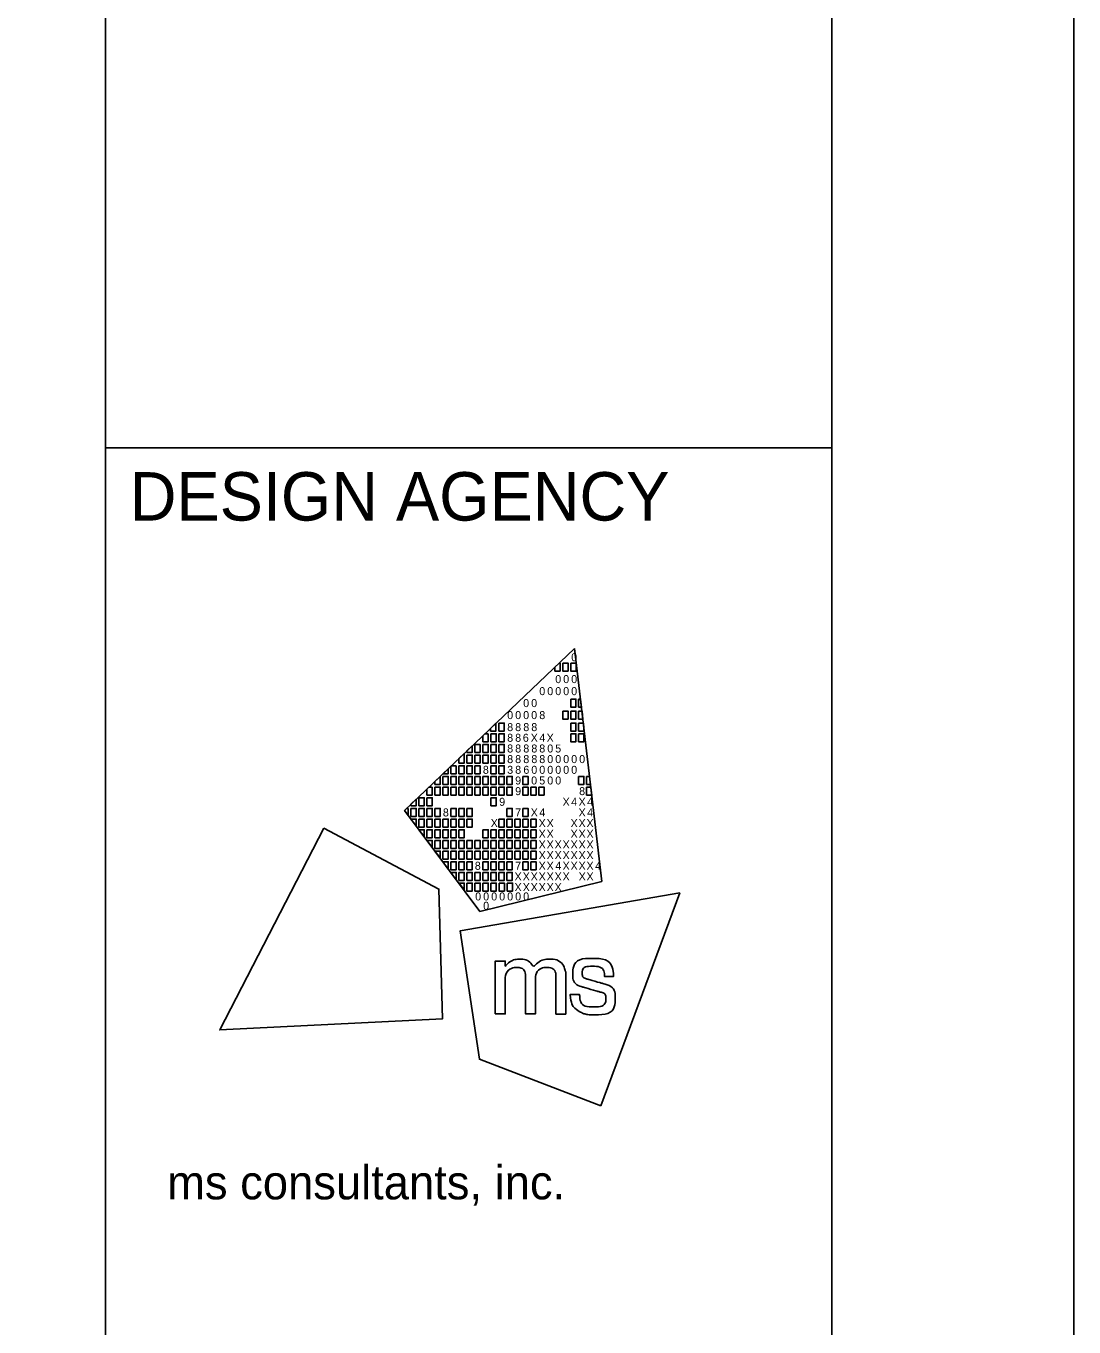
# Model space of a CAD drawing. Extents: x -0.6 to 34, y 0 to 22.
# Drawn here: x 31.836 to 34, y 2.685 to 5.371 of the extents above; entities that cross this region are included whole.
import ezdxf

# ---------------------------------------------------------------- set-up
doc = ezdxf.new("R2010")
doc.units = 0
for name, color, linetype in [('Default', 7, 'Continuous'), ('SH_Border', 7, 'Continuous'), ('SH_Cut_Line', 7, 'Continuous'), ('SH_Data', 7, 'Continuous')]:
    doc.layers.add(name, color=color, linetype=linetype)

msp = doc.modelspace()

# ---------------------------------------------------------------- linework, layer by layer
at = {"layer": 'Default'}
for p, q in [((32.6175, 3.7519), (32.9688, 4.0861)), ((32.9688, 4.0861), (32.9688, 4.0861)), ((32.9688, 4.0861), (33.0253, 3.6052)), ((32.773, 3.543), (32.6175, 3.7519)), ((33.0253, 3.6052), (32.773, 3.543))]:
    msp.add_line(p, q, dxfattribs=at)
for points in [[(32.9279, 4.0472), (32.9369, 4.0558), (32.9389, 4.0558), (32.9389, 4.0393), (32.9279, 4.0393)], [(32.9444, 4.0558), (32.9554, 4.0558), (32.9554, 4.0393), (32.9444, 4.0393)], [(32.9609, 4.0558), (32.9719, 4.0558), (32.9719, 4.0393), (32.9609, 4.0393)], [(32.9606, 3.9815), (32.9716, 3.9815), (32.9716, 3.965), (32.9606, 3.965)], [(32.9771, 3.9815), (32.9811, 3.9815), (32.983, 3.965), (32.9771, 3.965)], [(32.9441, 3.9567), (32.9551, 3.9567), (32.9551, 3.9402), (32.9441, 3.9402)], [(32.9606, 3.9567), (32.9716, 3.9567), (32.9716, 3.9402), (32.9606, 3.9402)], [(32.9771, 3.9567), (32.984, 3.9567), (32.9859, 3.9402), (32.9771, 3.9402)], [(32.7953, 3.9211), (32.8064, 3.9316), (32.8064, 3.9154), (32.7953, 3.9154)], [(32.8123, 3.9319), (32.8233, 3.9319), (32.8233, 3.9154), (32.8123, 3.9154)], [(32.9606, 3.9319), (32.9716, 3.9319), (32.9716, 3.9154), (32.9606, 3.9154)], [(32.9771, 3.9319), (32.9869, 3.9319), (32.9881, 3.9218), (32.9881, 3.9154), (32.9771, 3.9154)], [(32.7958, 3.9099), (32.8068, 3.9099), (32.8068, 3.8934), (32.7958, 3.8934)], [(32.8123, 3.9099), (32.8233, 3.9099), (32.8233, 3.8934), (32.8123, 3.8934)], [(32.9606, 3.9099), (32.9716, 3.9099), (32.9716, 3.8934), (32.9606, 3.8934)], [(32.9771, 3.9099), (32.9881, 3.9099), (32.9881, 3.8934), (32.9771, 3.8934)], [(32.7627, 3.8879), (32.7737, 3.8879), (32.7737, 3.8714), (32.7627, 3.8714)], [(32.7793, 3.8879), (32.7903, 3.8879), (32.7903, 3.8714), (32.7793, 3.8714)], [(32.7958, 3.8879), (32.8068, 3.8879), (32.8068, 3.8714), (32.7958, 3.8714)], [(32.8123, 3.8879), (32.8233, 3.8879), (32.8233, 3.8714), (32.8123, 3.8714)], [(32.7297, 3.8439), (32.7407, 3.8439), (32.7407, 3.8273), (32.7297, 3.8273)], [(32.7462, 3.8659), (32.7572, 3.8659), (32.7572, 3.8494), (32.7462, 3.8494)], [(32.7462, 3.8439), (32.7572, 3.8439), (32.7572, 3.8273), (32.7462, 3.8273)], [(32.7627, 3.8659), (32.7737, 3.8659), (32.7737, 3.8494), (32.7627, 3.8494)], [(32.7627, 3.8439), (32.7737, 3.8439), (32.7737, 3.8273), (32.7627, 3.8273)], [(32.7793, 3.8659), (32.7903, 3.8659), (32.7903, 3.8494), (32.7793, 3.8494)], [(32.7958, 3.8659), (32.8068, 3.8659), (32.8068, 3.8494), (32.7958, 3.8494)], [(32.7958, 3.8439), (32.8068, 3.8439), (32.8068, 3.8273), (32.7958, 3.8273)], [(32.8123, 3.8659), (32.8233, 3.8659), (32.8233, 3.8494), (32.8123, 3.8494)], [(32.8123, 3.8439), (32.8233, 3.8439), (32.8233, 3.8273), (32.8123, 3.8273)], [(32.6967, 3.8218), (32.7077, 3.8218), (32.7077, 3.8053), (32.6967, 3.8053)], [(32.7132, 3.8218), (32.7242, 3.8218), (32.7242, 3.8053), (32.7132, 3.8053)], [(32.7297, 3.8218), (32.7407, 3.8218), (32.7407, 3.8053), (32.7297, 3.8053)], [(32.7462, 3.8218), (32.7572, 3.8218), (32.7572, 3.8053), (32.7462, 3.8053)], [(32.7627, 3.8218), (32.7737, 3.8218), (32.7737, 3.8053), (32.7627, 3.8053)], [(32.7793, 3.8218), (32.7903, 3.8218), (32.7903, 3.8053), (32.7793, 3.8053)], [(32.7958, 3.8218), (32.8068, 3.8218), (32.8068, 3.8053), (32.7958, 3.8053)], [(32.8123, 3.8218), (32.8233, 3.8218), (32.8233, 3.8053), (32.8123, 3.8053)], [(32.8288, 3.8218), (32.8398, 3.8218), (32.8398, 3.8053), (32.8288, 3.8053)], [(32.8618, 3.8218), (32.8728, 3.8218), (32.8728, 3.8053), (32.8618, 3.8053)], [(32.9771, 3.8218), (32.9881, 3.8218), (32.9881, 3.8053), (32.9771, 3.8053)], [(32.9935, 3.8218), (32.9998, 3.8218), (33.0018, 3.8053), (32.9935, 3.8053)], [(32.6802, 3.7998), (32.6912, 3.7998), (32.6912, 3.7833), (32.6802, 3.7833)], [(32.6967, 3.7998), (32.7077, 3.7998), (32.7077, 3.7833), (32.6967, 3.7833)], [(32.7132, 3.7998), (32.7242, 3.7998), (32.7242, 3.7833), (32.7132, 3.7833)], [(32.7297, 3.7998), (32.7407, 3.7998), (32.7407, 3.7833), (32.7297, 3.7833)], [(32.7462, 3.7998), (32.7572, 3.7998), (32.7572, 3.7833), (32.7462, 3.7833)], [(32.7627, 3.7998), (32.7737, 3.7998), (32.7737, 3.7833), (32.7627, 3.7833)], [(32.7793, 3.7998), (32.7903, 3.7998), (32.7903, 3.7833), (32.7793, 3.7833)], [(32.7958, 3.7998), (32.8068, 3.7998), (32.8068, 3.7833), (32.7958, 3.7833)], [(32.8123, 3.7998), (32.8233, 3.7998), (32.8233, 3.7833), (32.8123, 3.7833)], [(32.8288, 3.7998), (32.8398, 3.7998), (32.8398, 3.7833), (32.8288, 3.7833)], [(32.8618, 3.7998), (32.8728, 3.7998), (32.8728, 3.7833), (32.8618, 3.7833)], [(32.8783, 3.7998), (32.8893, 3.7998), (32.8893, 3.7833), (32.8783, 3.7833)], [(32.8947, 3.7998), (32.9057, 3.7998), (32.9057, 3.7833), (32.8947, 3.7833)], [(32.9935, 3.7998), (33.0024, 3.7998), (33.0044, 3.7833), (32.9935, 3.7833)], [(32.6471, 3.7778), (32.6581, 3.7778), (32.6581, 3.7613), (32.6471, 3.7613)], [(32.6637, 3.7778), (32.6747, 3.7778), (32.6747, 3.7613), (32.6637, 3.7613)], [(32.7958, 3.7778), (32.8068, 3.7778), (32.8068, 3.7613), (32.7958, 3.7613)], [(32.6306, 3.7558), (32.6416, 3.7558), (32.6416, 3.7393), (32.6306, 3.7393)], [(32.6306, 3.7338), (32.6416, 3.7338), (32.6416, 3.72)], [(32.6471, 3.7558), (32.6581, 3.7558), (32.6581, 3.7393), (32.6471, 3.7393)], [(32.6471, 3.7338), (32.6581, 3.7338), (32.6581, 3.7173), (32.6471, 3.7173)], [(32.6637, 3.7558), (32.6747, 3.7558), (32.6747, 3.7393), (32.6637, 3.7393)], [(32.6637, 3.7338), (32.6747, 3.7338), (32.6747, 3.7173), (32.6637, 3.7173)], [(32.6802, 3.7558), (32.6912, 3.7558), (32.6912, 3.7393), (32.6802, 3.7393)], [(32.6802, 3.7338), (32.6912, 3.7338), (32.6912, 3.7173), (32.6802, 3.7173)], [(32.6967, 3.7338), (32.7077, 3.7338), (32.7077, 3.7173), (32.6967, 3.7173)], [(32.7132, 3.7558), (32.7242, 3.7558), (32.7242, 3.7393), (32.7132, 3.7393)], [(32.7132, 3.7338), (32.7242, 3.7338), (32.7242, 3.7173), (32.7132, 3.7173)], [(32.7297, 3.7558), (32.7407, 3.7558), (32.7407, 3.7393), (32.7297, 3.7393)], [(32.7297, 3.7338), (32.7407, 3.7338), (32.7407, 3.7173), (32.7297, 3.7173)], [(32.7462, 3.7558), (32.7572, 3.7558), (32.7572, 3.7393), (32.7462, 3.7393)], [(32.7462, 3.7338), (32.7572, 3.7338), (32.7572, 3.7173), (32.7462, 3.7173)], [(32.8123, 3.7338), (32.8233, 3.7338), (32.8233, 3.7173), (32.8123, 3.7173)], [(32.8288, 3.7558), (32.8398, 3.7558), (32.8398, 3.7393), (32.8288, 3.7393)], [(32.8288, 3.7338), (32.8398, 3.7338), (32.8398, 3.7173), (32.8288, 3.7173)], [(32.8453, 3.7338), (32.8563, 3.7338), (32.8563, 3.7173), (32.8453, 3.7173)], [(32.8618, 3.7558), (32.8728, 3.7558), (32.8728, 3.7393), (32.8618, 3.7393)], [(32.8618, 3.7338), (32.8728, 3.7338), (32.8728, 3.7173), (32.8618, 3.7173)], [(32.8783, 3.7338), (32.8893, 3.7338), (32.8893, 3.7173), (32.8783, 3.7173)], [(32.6471, 3.7117), (32.6581, 3.7117), (32.6581, 3.698)], [(32.6637, 3.7117), (32.6747, 3.7117), (32.6747, 3.6952), (32.6637, 3.6952)], [(32.6802, 3.7117), (32.6912, 3.7117), (32.6912, 3.6952), (32.6802, 3.6952)], [(32.6967, 3.7117), (32.7077, 3.7117), (32.7077, 3.6952), (32.6967, 3.6952)], [(32.7132, 3.7117), (32.7242, 3.7117), (32.7242, 3.6952), (32.7132, 3.6952)], [(32.7297, 3.7117), (32.7407, 3.7117), (32.7407, 3.6952), (32.7297, 3.6952)], [(32.7793, 3.7117), (32.7903, 3.7117), (32.7903, 3.6952), (32.7793, 3.6952)], [(32.7958, 3.7117), (32.8068, 3.7117), (32.8068, 3.6952), (32.7958, 3.6952)], [(32.8123, 3.7117), (32.8233, 3.7117), (32.8233, 3.6952), (32.8123, 3.6952)], [(32.8288, 3.7117), (32.8398, 3.7117), (32.8398, 3.6952), (32.8288, 3.6952)], [(32.8453, 3.7117), (32.8563, 3.7117), (32.8563, 3.6952), (32.8453, 3.6952)], [(32.8618, 3.7117), (32.8728, 3.7117), (32.8728, 3.6952), (32.8618, 3.6952)], [(32.8783, 3.7117), (32.8893, 3.7117), (32.8893, 3.6952), (32.8783, 3.6952)], [(32.6637, 3.6897), (32.6747, 3.6897), (32.6747, 3.676)], [(32.6747, 3.6897), (32.6747, 3.6897), (32.6747, 3.6897)], [(32.6802, 3.6897), (32.6912, 3.6897), (32.6912, 3.6732), (32.6802, 3.6732)], [(32.6967, 3.6897), (32.7077, 3.6897), (32.7077, 3.6732), (32.6967, 3.6732)], [(32.7132, 3.6897), (32.7242, 3.6897), (32.7242, 3.6732), (32.7132, 3.6732)], [(32.7297, 3.6897), (32.7407, 3.6897), (32.7407, 3.6732), (32.7297, 3.6732)], [(32.7462, 3.6897), (32.7572, 3.6897), (32.7572, 3.6732), (32.7462, 3.6732)], [(32.7627, 3.6897), (32.7737, 3.6897), (32.7737, 3.6732), (32.7627, 3.6732)], [(32.7793, 3.6897), (32.7903, 3.6897), (32.7903, 3.6732), (32.7793, 3.6732)], [(32.7958, 3.6897), (32.8068, 3.6897), (32.8068, 3.6732), (32.7958, 3.6732)], [(32.8123, 3.6897), (32.8233, 3.6897), (32.8233, 3.6732), (32.8123, 3.6732)], [(32.8288, 3.6897), (32.8398, 3.6897), (32.8398, 3.6732), (32.8288, 3.6732)], [(32.8453, 3.6897), (32.8563, 3.6897), (32.8563, 3.6732), (32.8453, 3.6732)], [(32.8618, 3.6897), (32.8728, 3.6897), (32.8728, 3.6732), (32.8618, 3.6732)], [(32.8783, 3.6897), (32.8893, 3.6897), (32.8893, 3.6732), (32.8783, 3.6732)], [(32.6802, 3.6677), (32.6912, 3.6677), (32.6912, 3.654)], [(32.6967, 3.6677), (32.7077, 3.6677), (32.7077, 3.6512), (32.6967, 3.6512)], [(32.7132, 3.6677), (32.7242, 3.6677), (32.7242, 3.6512), (32.7132, 3.6512)], [(32.7297, 3.6677), (32.7407, 3.6677), (32.7407, 3.6512), (32.7297, 3.6512)], [(32.7462, 3.6677), (32.7572, 3.6677), (32.7572, 3.6512), (32.7462, 3.6512)], [(32.7627, 3.6677), (32.7737, 3.6677), (32.7737, 3.6512), (32.7627, 3.6512)], [(32.7793, 3.6677), (32.7903, 3.6677), (32.7903, 3.6512), (32.7793, 3.6512)], [(32.7958, 3.6677), (32.8068, 3.6677), (32.8068, 3.6512), (32.7958, 3.6512)], [(32.8123, 3.6677), (32.8233, 3.6677), (32.8233, 3.6512), (32.8123, 3.6512)], [(32.8288, 3.6677), (32.8398, 3.6677), (32.8398, 3.6512), (32.8288, 3.6512)], [(32.8453, 3.6677), (32.8563, 3.6677), (32.8563, 3.6512), (32.8453, 3.6512)], [(32.8618, 3.6677), (32.8728, 3.6677), (32.8728, 3.6512), (32.8618, 3.6512)], [(32.8783, 3.6677), (32.8893, 3.6677), (32.8893, 3.6512), (32.8783, 3.6512)], [(32.7077, 3.6305), (32.6965, 3.6457), (32.7077, 3.6457)], [(32.7132, 3.6457), (32.7242, 3.6457), (32.7242, 3.6292), (32.7132, 3.6292)], [(32.7297, 3.6457), (32.7407, 3.6457), (32.7407, 3.6292), (32.7297, 3.6292)], [(32.7462, 3.6457), (32.7572, 3.6457), (32.7572, 3.6292), (32.7462, 3.6292)], [(32.7793, 3.6457), (32.7903, 3.6457), (32.7903, 3.6292), (32.7793, 3.6292)], [(32.7958, 3.6457), (32.8068, 3.6457), (32.8068, 3.6292), (32.7958, 3.6292)], [(32.8123, 3.6457), (32.8233, 3.6457), (32.8233, 3.6292), (32.8123, 3.6292)], [(32.8288, 3.6457), (32.8398, 3.6457), (32.8398, 3.6292), (32.8288, 3.6292)], [(32.8618, 3.6457), (32.8728, 3.6457), (32.8728, 3.6292), (32.8618, 3.6292)], [(32.8783, 3.6457), (32.8893, 3.6457), (32.8893, 3.6292), (32.8783, 3.6292)], [(32.724, 3.6082), (32.7132, 3.6237), (32.7242, 3.6237)], [(32.7297, 3.6237), (32.7407, 3.6237), (32.7407, 3.6072), (32.7297, 3.6072)], [(32.7302, 3.6017), (32.7407, 3.6017), (32.7408, 3.5875)], [(32.7462, 3.6237), (32.7572, 3.6237), (32.7572, 3.6072), (32.7462, 3.6072)], [(32.7463, 3.6017), (32.7573, 3.6017), (32.7573, 3.5852), (32.7463, 3.5852)], [(32.7627, 3.6237), (32.7737, 3.6237), (32.7737, 3.6072), (32.7627, 3.6072)], [(32.763, 3.6017), (32.774, 3.6017), (32.774, 3.5852), (32.763, 3.5852)], [(32.7793, 3.6237), (32.7903, 3.6237), (32.7903, 3.6072), (32.7793, 3.6072)], [(32.7794, 3.6017), (32.7904, 3.6017), (32.7904, 3.5852), (32.7794, 3.5852)], [(32.7958, 3.6237), (32.8068, 3.6237), (32.8068, 3.6072), (32.7958, 3.6072)], [(32.796, 3.6017), (32.807, 3.6017), (32.807, 3.5852), (32.796, 3.5852)], [(32.8123, 3.6237), (32.8233, 3.6237), (32.8233, 3.6072), (32.8123, 3.6072)], [(32.8129, 3.6017), (32.8239, 3.6017), (32.8239, 3.5851), (32.8129, 3.5851)], [(32.8288, 3.6237), (32.8398, 3.6237), (32.8398, 3.6072), (32.8288, 3.6072)], [(32.8296, 3.6017), (32.8406, 3.6017), (32.8406, 3.5851), (32.8296, 3.5851)]]:
    msp.add_lwpolyline(points, close=True, dxfattribs=at)
for points in [[(32.7903, 3.9099), (32.7836, 3.9099), (32.7793, 3.9058), (32.7793, 3.8934), (32.7903, 3.8934), (32.7903, 3.9099)], [(32.7407, 3.8691), (32.7297, 3.8587), (32.7297, 3.8494), (32.7407, 3.8494), (32.7407, 3.8691)], [(32.7572, 3.8849), (32.7462, 3.8744), (32.7462, 3.8714), (32.7572, 3.8714), (32.7572, 3.8849)], [(32.7242, 3.8439), (32.7141, 3.8439), (32.7132, 3.843), (32.7132, 3.8273), (32.7242, 3.8273), (32.7242, 3.8439)], [(32.6912, 3.822), (32.6802, 3.8115), (32.6802, 3.8053), (32.6912, 3.8053), (32.6912, 3.822)], [(32.7077, 3.8377), (32.6968, 3.8273), (32.7077, 3.8273), (32.7077, 3.8377)], [(32.6747, 3.7998), (32.6679, 3.7998), (32.6637, 3.7958), (32.6637, 3.7833), (32.6747, 3.7833), (32.6747, 3.7998)], [(32.6416, 3.7749), (32.6306, 3.7644), (32.6306, 3.7613), (32.6416, 3.7613), (32.6416, 3.7749)], [(32.6251, 3.7558), (32.6216, 3.7558), (32.6175, 3.7519), (32.6251, 3.7417), (32.6251, 3.7558)], [(32.4512, 3.7149), (32.2359, 3.2988), (32.6956, 3.3215), (32.6884, 3.5892), (32.4512, 3.7149)], [(33.0229, 3.1422), (33.1859, 3.5814), (32.7324, 3.5029), (32.7722, 3.2381), (33.0229, 3.1422)]]:
    msp.add_lwpolyline(points, dxfattribs=at)
for points in [[(32.8048, 3.3315), (32.8048, 3.3315), (32.8048, 3.4409), (32.8048, 3.4409), (32.8048, 3.4409), (32.8255, 3.4409), (32.8255, 3.4409), (32.8255, 3.4409), (32.8255, 3.4297), (32.8255, 3.4297), (32.8346, 3.4399), (32.8457, 3.4445), (32.8555, 3.4445), (32.8688, 3.4445), (32.8791, 3.4372), (32.8837, 3.4266), (32.8915, 3.4381), (32.905, 3.4446), (32.9166, 3.4446), (32.9325, 3.4446), (32.9451, 3.435), (32.9494, 3.4213), (32.9494, 3.4212), (32.9494, 3.4212), (32.9494, 3.4212), (32.9501, 3.419), (32.9506, 3.4172), (32.9506, 3.4071), (32.9506, 3.4071), (32.9506, 3.3314), (32.9506, 3.3314), (32.9506, 3.3314), (32.9303, 3.3314), (32.9303, 3.3314), (32.9303, 3.3314), (32.9303, 3.4048), (32.9303, 3.4048), (32.9303, 3.4201), (32.9219, 3.4274), (32.911, 3.4274), (32.8995, 3.4274), (32.8879, 3.4171), (32.8879, 3.4001), (32.8879, 3.4001), (32.8879, 3.3315), (32.8879, 3.3315), (32.8879, 3.3315), (32.8674, 3.3315), (32.8674, 3.3315), (32.8674, 3.3315), (32.8674, 3.4059), (32.8674, 3.4059), (32.8674, 3.4203), (32.8588, 3.4274), (32.8496, 3.4274), (32.8384, 3.4274), (32.8254, 3.417), (32.8254, 3.3962), (32.8254, 3.3962), (32.8254, 3.3315), (32.8254, 3.3315), (32.8254, 3.3315), (32.8048, 3.3315), (32.8048, 3.3315)], [(32.9595, 3.3709), (32.9595, 3.3709), (32.9595, 3.3717), (32.9595, 3.3717), (32.9595, 3.3717), (32.9603, 3.3717), (32.9603, 3.3717), (32.9603, 3.3717), (32.9783, 3.3717), (32.9783, 3.3717), (32.9783, 3.3717), (32.9789, 3.3717), (32.9789, 3.3717), (32.9789, 3.3717), (32.979, 3.371), (32.979, 3.371), (32.9803, 3.3554), (32.9887, 3.346), (33.009, 3.346), (33.0273, 3.346), (33.0333, 3.3554), (33.0333, 3.3631), (33.0333, 3.3732), (33.0256, 3.3758), (33.0175, 3.378), (33.0175, 3.378), (32.987, 3.3867), (32.987, 3.3867), (32.972, 3.3909), (32.9648, 3.4019), (32.9648, 3.4142), (32.9648, 3.4303), (32.9768, 3.4462), (33.0052, 3.4462), (33.0348, 3.4462), (33.0489, 3.4285), (33.0489, 3.4095), (33.0489, 3.4095), (33.0489, 3.4087), (33.0489, 3.4087), (33.0489, 3.4087), (33.0482, 3.4087), (33.0482, 3.4087), (33.0482, 3.4087), (33.0312, 3.4087), (33.0312, 3.4087), (33.0312, 3.4087), (33.0305, 3.4087), (33.0305, 3.4087), (33.0305, 3.4087), (33.0305, 3.4094), (33.0305, 3.4094), (33.0301, 3.4208), (33.0226, 3.43), (33.0056, 3.43), (32.9891, 3.43), (32.9843, 3.4218), (32.9843, 3.4157), (32.9843, 3.4108), (32.9869, 3.4059), (32.9959, 3.4033), (32.9959, 3.4033), (33.0255, 3.3948), (33.0255, 3.3948), (33.0462, 3.3889), (33.0527, 3.3777), (33.0527, 3.3639), (33.0527, 3.3462), (33.041, 3.3298), (33.0087, 3.3298), (32.9952, 3.3298), (32.9877, 3.3321), (32.9823, 3.3348), (32.969, 3.3414), (32.9609, 3.3536), (32.9595, 3.3709)]]:
    msp.add_open_spline(points, degree=3, dxfattribs=at)
at = {"layer": 'SH_Border'}
for p, q in [((32, 0.5), (32, 21.5)), ((32, 4.5), (33.5, 4.5))]:
    msp.add_line(p, q, dxfattribs=at)
msp.add_lwpolyline([(1.5, 21.5), (33.5, 21.5), (33.5, 0.5), (1.5, 0.5)], close=True, dxfattribs=at)
at = {"layer": 'SH_Cut_Line'}
msp.add_lwpolyline([(0, 0), (34, 0), (34, 22), (0, 22)], close=True, dxfattribs=at)
at = {"layer": 'SH_Data'}
msp.add_line((32.75, 3.5), (32.75, 3.5), dxfattribs=at)

# ---------------------------------------------------------------- texts
at = {"layer": 'Default'}
for s, p in [('0', (32.9617, 4.0597)), ('0', (32.9288, 4.0145)), ('0', (32.9452, 4.0145)), ('0', (32.9617, 4.0145)), ('0', (32.8958, 3.9897)), ('0', (32.9123, 3.9897)), ('0', (32.9288, 3.9897)), ('0', (32.9452, 3.9897)), ('0', (32.9617, 3.9897)), ('0', (32.8625, 3.965)), ('0', (32.879, 3.965)), ('0', (32.8295, 3.9402)), ('0', (32.846, 3.9402)), ('0', (32.8625, 3.9402)), ('0', (32.879, 3.9402)), ('8', (32.8958, 3.9402)), ('8', (32.8295, 3.9154)), ('8', (32.846, 3.9154)), ('8', (32.8628, 3.9154)), ('8', (32.8793, 3.9154)), ('8', (32.8295, 3.8934)), ('8', (32.846, 3.8934)), ('6', (32.8618, 3.8934)), ('X', (32.8781, 3.8934)), ('4', (32.8958, 3.8934)), ('X', (32.911, 3.8934)), ('8', (32.8295, 3.8713)), ('8', (32.846, 3.8713)), ('8', (32.8628, 3.8713)), ('8', (32.8794, 3.8713)), ('8', (32.8958, 3.8713)), ('0', (32.9123, 3.8713)), ('5', (32.9287, 3.8713)), ('8', (32.7793, 3.8273)), ('3', (32.8295, 3.8273)), ('8', (32.8295, 3.8494)), ('8', (32.846, 3.8494)), ('8', (32.846, 3.8273)), ('8', (32.8628, 3.8494)), ('6', (32.8629, 3.8273)), ('0', (32.8793, 3.8273)), ('8', (32.8794, 3.8494)), ('8', (32.8958, 3.8494)), ('0', (32.8958, 3.8273)), ('0', (32.9123, 3.8494)), ('0', (32.9123, 3.8273)), ('0', (32.9288, 3.8494)), ('0', (32.9288, 3.8273)), ('0', (32.9452, 3.8494)), ('0', (32.9452, 3.8273)), ('0', (32.9617, 3.8494)), ('0', (32.9617, 3.8273)), ('0', (32.9782, 3.8494)), ('9', (32.846, 3.8053)), ('0', (32.879, 3.8053)), ('5', (32.8957, 3.8053)), ('0', (32.9123, 3.8053)), ('0', (32.9288, 3.8053)), ('9', (32.846, 3.7833)), ('8', (32.9781, 3.7833)), ('9', (32.813, 3.7613)), ('X', (32.9439, 3.7613)), ('4', (32.9617, 3.7613)), ('X', (32.9769, 3.7613)), ('4', (32.9946, 3.7613)), ('8', (32.6967, 3.7393)), ('X', (32.7955, 3.7173)), ('7', (32.846, 3.7393)), ('X', (32.8781, 3.7393)), ('X', (32.8945, 3.7173)), ('4', (32.8958, 3.7393)), ('X', (32.911, 3.7173)), ('X', (32.9604, 3.7173)), ('X', (32.9769, 3.7393)), ('X', (32.9769, 3.7173)), ('X', (32.9933, 3.7173)), ('4', (32.9946, 3.7393)), ('X', (32.8945, 3.6952)), ('X', (32.911, 3.6952)), ('X', (32.9604, 3.6952)), ('X', (32.9769, 3.6952)), ('X', (32.9933, 3.6952)), ('X', (32.8945, 3.6732)), ('X', (32.911, 3.6732)), ('X', (32.9274, 3.6732)), ('X', (32.9439, 3.6732)), ('X', (32.9604, 3.6732)), ('X', (32.9769, 3.6732)), ('X', (32.9933, 3.6732)), ('X', (32.8945, 3.6512)), ('X', (32.911, 3.6512)), ('X', (32.9274, 3.6512)), ('X', (32.9439, 3.6512)), ('X', (32.9604, 3.6512)), ('X', (32.9769, 3.6512)), ('X', (32.9933, 3.6512)), ('8', (32.7627, 3.6292)), ('7', (32.846, 3.6292)), ('X', (32.8945, 3.6292)), ('X', (32.911, 3.6292)), ('4', (32.9288, 3.6292)), ('X', (32.9439, 3.6292)), ('X', (32.9604, 3.6292)), ('X', (32.9769, 3.6292)), ('X', (32.9933, 3.6292)), ('4', (33.0111, 3.6292)), ('X', (32.8447, 3.6072)), ('X', (32.8447, 3.5851)), ('X', (32.8616, 3.6072)), ('X', (32.8616, 3.5851)), ('X', (32.878, 3.6072)), ('X', (32.878, 3.5851)), ('X', (32.8945, 3.6072)), ('X', (32.8945, 3.5851)), ('X', (32.911, 3.6072)), ('X', (32.911, 3.5851)), ('X', (32.9274, 3.6072)), ('X', (32.9274, 3.5851)), ('X', (32.9439, 3.6072)), ('X', (32.9771, 3.6072)), ('X', (32.9933, 3.6072)), ('0', (32.7634, 3.5659)), ('0', (32.7799, 3.5659)), ('0', (32.7965, 3.5659)), ('0', (32.813, 3.5659)), ('0', (32.8295, 3.5659)), ('0', (32.846, 3.5659)), ('0', (32.8625, 3.5659)), ('0', (32.7799, 3.5467))]:
    msp.add_text(s, height=0.0165, rotation=360, dxfattribs=at).set_placement(p)
at = {"layer": 'SH_Border'}
msp.add_text('ms consultants, inc.', height=0.07, rotation=360, dxfattribs=at).set_placement((32.1273, 2.9489))
at = {"layer": 'SH_Data'}
msp.add_text('DESIGN AGENCY', height=0.1, dxfattribs=at).set_placement((32.05, 4.35))

doc.saveas('drawing.dxf')
